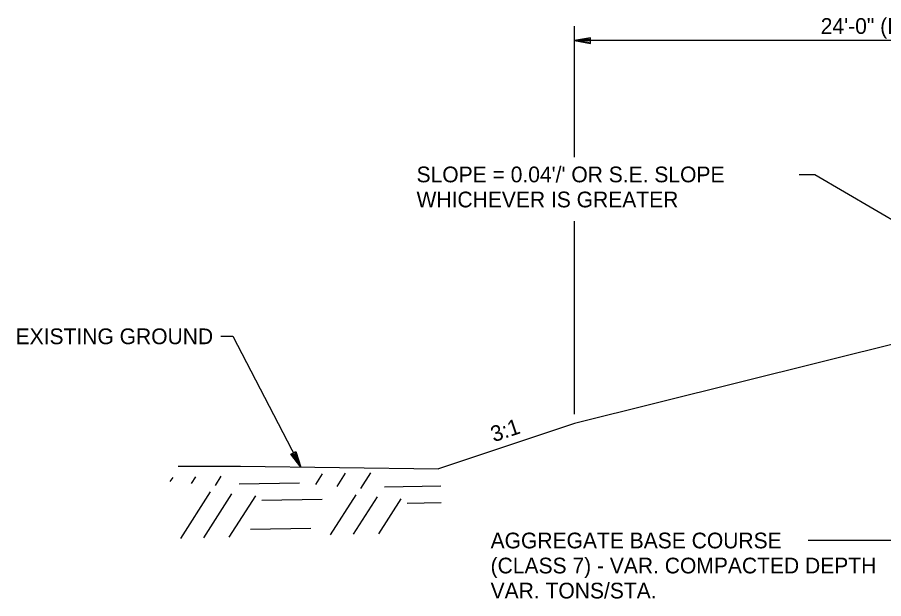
# Model space of a CAD drawing. Extents: x 1398183 to 1398373, y 1967240 to 1968889.
# Drawn here: x 1398192.77 to 1398225.26, y 1968333.87 to 1968355.68 of the extents above; entities that cross this region are included whole.
import ezdxf

# ---------------------------------------------------------------- set-up
doc = ezdxf.new("R2010")
doc.units = 0
for name, color, linetype in [('10', 7, 'Continuous'), ('19', 7, 'Continuous'), ('42', 7, 'Continuous'), ('9', 7, 'Continuous')]:
    doc.layers.add(name, color=color, linetype=linetype)

msp = doc.modelspace()

# ---------------------------------------------------------------- linework, layer by layer
at = {"layer": '19'}
for p, q in [((1398213.673, 1968350.438), (1398213.673, 1968355.358)), ((1398214.273, 1968354.916), (1398213.673, 1968354.811)), ((1398214.273, 1968354.861), (1398213.833, 1968354.826)), ((1398214.273, 1968354.706), (1398214.273, 1968354.916)), ((1398237.673, 1968354.811), (1398213.673, 1968354.811)), ((1398213.673, 1968354.811), (1398214.273, 1968354.706)), ((1398213.833, 1968354.796), (1398214.273, 1968354.756)), ((1398222.091, 1968349.789), (1398222.681, 1968349.789)), ((1398222.681, 1968349.789), (1398231.609, 1968344.541)), ((1398213.673, 1968340.796), (1398213.673, 1968348.036)), ((1398229.673, 1968344.439), (1398213.673, 1968340.439)), ((1398213.673, 1968340.439), (1398208.572, 1968338.738)), ((1398203.035, 1968339.292), (1398203.22, 1968339.388)), ((1398203.404, 1968338.808), (1398203.035, 1968339.292)), ((1398203.322, 1968338.944), (1398203.085, 1968339.313)), ((1398203.181, 1968339.364), (1398203.343, 1968338.958)), ((1398203.22, 1968339.388), (1398203.404, 1968338.808)), ((1398222.427, 1968336.062), (1398227.444, 1968336.062))]:
    msp.add_line(p, q, dxfattribs=at)
msp.add_lwpolyline([(1398200.405, 1968343.715), (1398200.851, 1968343.715), (1398203.404, 1968338.808)], dxfattribs=at)
at = {"layer": '42'}
msp.add_lwpolyline([(1398198.803, 1968338.839), (1398201.141, 1968338.839), (1398208.572, 1968338.738)], dxfattribs=at)
at = {"layer": '9'}
for p, q in [((1398205.657, 1968338.008), (1398206.034, 1968338.598)), ((1398198.51, 1968338.265), (1398198.611, 1968338.421)), ((1398199.31, 1968338.191), (1398199.47, 1968338.441)), ((1398200.202, 1968338.119), (1398200.422, 1968338.464)), ((1398203.965, 1968338.153), (1398204.222, 1968338.555)), ((1398204.765, 1968338.08), (1398205.082, 1968338.575)), ((1398201.09, 1968338.178), (1398203.352, 1968338.213)), ((1398206.545, 1968338.066), (1398208.651, 1968338.099)), ((1398198.907, 1968336.133), (1398200.022, 1968337.874)), ((1398199.766, 1968336.153), (1398200.821, 1968337.8)), ((1398200.719, 1968336.176), (1398201.713, 1968337.729)), ((1398204.519, 1968336.267), (1398205.477, 1968337.763)), ((1398205.378, 1968336.287), (1398206.276, 1968337.689)), ((1398201.939, 1968337.567), (1398204.201, 1968337.602)), ((1398206.33, 1968336.31), (1398207.168, 1968337.617)), ((1398207.394, 1968337.456), (1398208.666, 1968337.476)), ((1398201.52, 1968336.481), (1398203.782, 1968336.516))]:
    msp.add_line(p, q, dxfattribs=at)

# ---------------------------------------------------------------- texts
at = {"layer": '10'}
for s, p in [('24\'-0" (FILL)', (1398222.904, 1968355.063)), ('EXISTING GROUND', (1398192.707, 1968343.42))]:
    msp.add_text(s, height=0.59001, dxfattribs=at).set_placement(p)
msp.add_text('3:1', height=0.59, rotation=18.4349, dxfattribs=at).set_placement((1398210.641, 1968339.739))
at = {"layer": '19'}
for s, p in [("SLOPE = 0.04'/' OR S.E. SLOPE", (1398207.745, 1968349.494)), ('WHICHEVER IS GREATER', (1398207.745, 1968348.554))]:
    msp.add_text(s, height=0.59001, dxfattribs=at).set_placement(p)
for s, p in [('AGGREGATE BASE COURSE', (1398210.522, 1968335.759)), ('(CLASS 7) - VAR. COMPACTED DEPTH', (1398210.522, 1968334.819)), ('VAR. TONS/STA.', (1398210.522, 1968333.879))]:
    msp.add_text(s, height=0.59001, rotation=360, dxfattribs=at).set_placement(p)

doc.saveas('drawing.dxf')
